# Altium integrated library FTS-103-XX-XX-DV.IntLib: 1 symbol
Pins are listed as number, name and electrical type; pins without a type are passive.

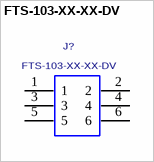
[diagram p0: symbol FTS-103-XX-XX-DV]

## FTS-103-XX-XX-DV
designator J?
0.050 INCH DOUBLE VERTICAL SMT TERMINAL STRIP.; MANUFACTURER: SAMTEC
footprint FTS-103-XX-XX-DV
pins: 1, 2, 3, 4, 5, 6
